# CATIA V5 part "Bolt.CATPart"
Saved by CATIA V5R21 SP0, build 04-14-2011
Part number: Bolt
Material "Nickel": density 8880 kg/m3, Young's modulus 2.14e+11 Pa, Poisson ratio 0.31, thermal expansion 1.31e-05 1/K
Material "Nickel": density 8880 kg/m3, Young's modulus 2.14e+11 Pa, Poisson ratio 0.31, thermal expansion 1.31e-05 1/K
Bounding box of the stored display mesh (mm): x -25.981 to 25.981, y -29.528 to 29.528, z 0 to 120
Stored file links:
  G:\CATIA\NUT BOLT\Bolt.CATPart
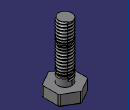
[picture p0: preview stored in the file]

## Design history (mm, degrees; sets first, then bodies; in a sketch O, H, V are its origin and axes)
AxisSystem1: origin (0, 0, 0), X (1, 0, 0), Y (0, 1, 0), Z (0, 0, 1)
Body1 (main body), material "Nickel"
  Sketch1 on XY plane of AxisSystem1, origin (0, 0, 0), H (0, 1, 0), V (-1, 0, 0)
    point P1 (15, 25.9808)
    point P2 (-15, 25.9808)
    point P3 (-30, 0)
    point P4 (-15, -25.9808)
    point P5 (15, -25.9808)
    point P6 (30, 0)
    point P7 (0, 25.9808)
    line L1 (15, 25.9808) -> (-15, 25.9808)
    line L2 (-15, 25.9808) -> (-30, 0)
    line L3 (-30, 0) -> (-15, -25.9808)
    line L4 (-15, -25.9808) -> (15, -25.9808)
    line L5 (15, -25.9808) -> (30, 0)
    line L6 (30, 0) -> (15, 25.9808)
    construction line L7 (0, 0) -> (0, 25.9808)
    construction circle A1 centre (0, 0) radius 30
    construction arc A2 centre (15, -25.9808) radius 30 from (-15, -25.9808) to (30, 0) cw
    construction arc A3 centre (-15, 25.9808) radius 30 from (-30, 0) to (15, 25.9808) ccw
    length L6 = 30
    vertical: L7 V
    coincidence: A1 P1, A1 P2, A1 P3, A1 P4, A1 P5, A1 P6, A2 O, A3 O
    midpoint: P7 L1
    parallelism: L1 L4
  Pad1: profile Sketch1, direction (0, 0, 1), length 20
  Sketch2 on end face of Pad1, origin (0, 0, 20), H (0, 1, 0), V (-1, 0, 0)
    circle A1 centre (0, 0) radius 12.5
    radius A1 = 12.5
  Pad2: profile Sketch2, direction (0, 0, 1), length 100
  Point1: type OnCurve, Support edge [face of Pad2 from Sketch2.A1 | end face of Pad2], RefPoint {extremum Reference edge [face of Pad2 from Sketch2.A1 | end face of Pad2], Direction (1, 2, 3)}, Length 0
  Fillet1: radius 3, on edge [face of Pad1 from Sketch1.L1 | face of Pad1 from Sketch1.L6]; edge [face of Pad1 from Sketch1.L6 | face of Pad1 from Sketch1.L5]; edge [face of Pad1 from Sketch1.L5 | face of Pad1 from Sketch1.L4]; edge [face of Pad1 from Sketch1.L4 | face of Pad1 from Sketch1.L3]; edge [face of Pad1 from Sketch1.L3 | face of Pad1 from Sketch1.L2]; edge [face of Pad1 from Sketch1.L2 | face of Pad1 from Sketch1.L1]
  Chamfer1: length 2, angle 45, on edge [start face of Pad1 | face of Pad1 from Sketch1.L5]
  Sketch3 on start face of Pad1, origin (0, 0, 0), H (0, -1, 0), V (-1, 0, 0)
    line L1 (-9.6079, 2.2761) -> (-9.6079, -2.7239)
    line L2 (-9.6079, -2.7239) -> (-2.3921, -2.7239)
    line L3 (-2.3921, -2.7239) -> (-2.3921, -9.7239)
    line L4 (-2.3921, -9.7239) -> (2.6079, -9.7239)
    line L5 (2.6079, -9.7239) -> (2.6079, -2.7239)
    point P6 (2.6079, -2.7239)
    line L6 (2.6079, -2.7239) -> (9.6079, -2.7239)
    line L7 (9.6079, -2.7239) -> (9.6079, 2.2761)
    line L8 (9.6079, 2.2761) -> (2.6079, 2.2761)
    point P9 (2.6079, 2.2761)
    line L9 (2.6079, 2.2761) -> (2.6079, 9.7239)
    line L10 (2.6079, 9.7239) -> (-2.3921, 9.7239)
    point P11 (-2.3921, 9.7239)
    line L11 (-2.3921, 9.7239) -> (-2.3921, 2.2761)
    point P12 (-2.3921, 2.2761)
    line L12 (-2.3921, 2.2761) -> (-9.6079, 2.2761)
    reference projected line E1 through (0, 0) direction (-1, 0) from edge [YZ plane of AxisSystem1 | XY plane of AxisSystem1]
    length L6 = 7
    length L5 = 7
    length L4 = 5
    length L7 = 5
    vertical: L1 V, L3 V, L5 V, L7 V, L9 V, L11 V
    horizontal: L2 H, L4 H, L6 H, L8 H, L10 H, L12 H
    coincidence: P6 L2, P9 L5, P11 L3, P12 L8
    symmetry: L7 L1 V, L4 L10 E1
  Pocket1: profile Sketch3, direction (0, 0, 1), length 10
  Chamfer2: length 1, angle 45, on edge [start face of Pad1 | face of Pocket1 from Sketch3.L2]; edge [start face of Pad1 | face of Pocket1 from Sketch3.L1]; edge [start face of Pad1 | face of Pocket1 from Sketch3.L12]; edge [start face of Pad1 | face of Pocket1 from Sketch3.L11]; edge [start face of Pad1 | face of Pocket1 from Sketch3.L10]; edge [start face of Pad1 | face of Pocket1 from Sketch3.L9]; edge [start face of Pad1 | face of Pocket1 from Sketch3.L8]; edge [start face of Pad1 | face of Pocket1 from Sketch3.L7]; edge [start face of Pad1 | face of Pocket1 from Sketch3.L6]; edge [start face of Pad1 | face of Pocket1 from Sketch3.L5]; edge [start face of Pad1 | face of Pocket1 from Sketch3.L4]; edge [start face of Pad1 | face of Pocket1 from Sketch3.L3]
  Helix1: Direction edge [ZX plane of AxisSystem1 | YZ plane of AxisSystem1], RefPoint Point1, Pitch 5, Height 90, TaperAngle 0
  Plane1: type Normal, Curve Helix1, RefPoint Point1
  Sketch4 on Plane1, origin (5.5902, 11.1803, 120), H (0.4472, 0.8944, 0), V (0.0568, -0.0284, 0.998)
    circle A1 centre (0, 0) radius 2
    radius A1 = 2
  Slot1: profile Sketch4, centre curve Helix1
